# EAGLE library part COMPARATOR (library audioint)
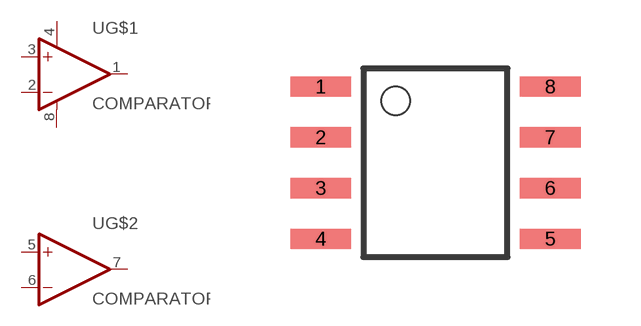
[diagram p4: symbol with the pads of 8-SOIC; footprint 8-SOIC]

Designator prefix -; gates G$1=OP-AMP-VCC G$2=OP-AMP

## COMPARATOR8-SOIC  [8-SOIC]
1  G$1:OUT  out
2  G$1:-IN  in
3  G$1:+IN  in
4  G$1:V-  pwr
5  G$2:+IN  in
6  G$2:-IN  in
7  G$2:OUT  out
8  G$1:V+  pwr

## Footprint 8-SOIC (pad centres in mm)
smd 1.524 x 0.508: 1 -2.87,1.905; 2 -2.87,0.635; 3 -2.87,-0.635; 4 -2.87,-1.905; 5 2.87,-1.905; 6 2.87,-0.635; 7 2.87,0.635; 8 2.87,1.905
